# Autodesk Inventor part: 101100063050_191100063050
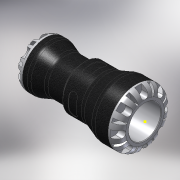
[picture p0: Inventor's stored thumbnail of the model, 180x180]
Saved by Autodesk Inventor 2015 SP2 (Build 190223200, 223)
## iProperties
Created: 2016-12
Part Number: 101100063050_191100063050
Material: PVC-Piping
Description: PLASSON REDUCING COUPLING 63X50 SERIES 1
Document SubType Name: Modeling
Designer: KIM
Mass: 811.92 g
Surface Area: 980.755 cm^2
Volume: 579.943 cm^3
Density: 1.4 g/cm^3
Appearance: Black Cast
Author: KIM
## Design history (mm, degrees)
derived "1011.ipt"
feature "Solid1::1011.ipt"
tag "TaggingFeature1"
body "Solid1"
other parameters: "d0" = 187, "d2" = 38.22, "d3" = 63, "d4" = 103, "d5" = 75.6, "d6" = 91, "d7" = 5.25, "d8" = 85, "d10" = 62.5, "d11" = 34.02, "d12" = 81, "d13" = 4.16667, "d14" = 82.4, "d15" = 68, "d16" = 20 deg, "d17" = 20 deg, "d18" = 130 deg, "d22" = 10.96, "d25" = 10.96, "d26" = 0, "d28" = 360 deg, "d30" = 8 deg, "d31" = 1.26, "d32" = 8 deg, "d33" = 1.26, "d35" = 0, "d37" = 360 deg, "d39" = 9, "d42" = 9, "d43" = 0, "d45" = 360 deg, "d47" = 1, "d48" = 8 deg, "d49" = 8 deg, "d50" = 1, "d52" = 0, "d54" = 360 deg, "d56" = 17, "d57" = 20.6, "d58" = 0.5, "d60" = 12.36, "d61" = 15.75, "d62" = 17.46, "d63" = 0, "d66" = 0, "d68" = 360 deg, "d75" = 11.03699, "d77" = 80.34, "d78" = 1.03, "d_" = 63, "E_" = 103, "H_" = 187, "l_" = 91, "E1" = 85, "l1" = 81, "Plasson" = 1, "d20" = 11.25, "d21" = 13.7, "d23" = 103, "d24" = 75.6, "d40" = 85, "d41" = 62.5, "d59" = 22.07398
